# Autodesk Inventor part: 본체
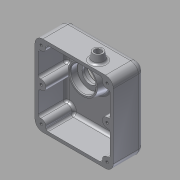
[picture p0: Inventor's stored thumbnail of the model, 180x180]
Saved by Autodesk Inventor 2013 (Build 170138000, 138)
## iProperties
Created: 2015-10
Part Number: 본체
Material: 알루미늄 6061
Document SubType Name: Modeling
Designer: mduedu
Density: 2.71 g/cm^3
Mass: 323.558 g
Surface Area: 515.791 cm^2
Volume: 119.394 cm^3
Author: mduedu
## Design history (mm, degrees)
sketch "스케치1"
  geometry: L1 (-50, -51.5)-(50, -51.5); L2 (50, -51.5)-(50, 51.5); L3 (50, 51.5)-(-50, 51.5); L4 (-50, 51.5)-(-50, -51.5); L5 (-50, -51.5)-(50, 51.5); L6 (50, -51.5)-(-50, 51.5); 1 further point
  constraints: 12 end point, 2 midpoint, 2 parallel, 1 horizontal, 1 perpendicular
  dimensions: "d0" = 100 distance of L3.end L2.end; "d1" = 103 distance of L2.end L1.end
extrude "돌출1" new body sketch "스케치1" distance "d2" = 40; taper "d3" = 0 deg
fillet "모깎기1" dims "d4" = 10
fillet "모깎기2" dims "d5" = 8
feature "쉘1" dims "d6" = 4
sketch "스케치2"
  geometry: L1 (-50, 41.5)-(-50, -41.5) reference; L2 (50, -41.5)-(50, 41.5) reference; L3 (-50, 0)-(50, 0); L4 (40, 51.5)-(-40, 51.5) reference; L5 (-40, -51.5)-(40, -51.5) reference; L6 (0, 51.5)-(0, -51.5); C1 r 6 at (-42, 43.5); C2 r 6 at (-42, 0); C3 r 6 at (-42, -43.5); C4 r 6 at (42, 43.5); C5 r 6 at (42, 0); C6 r 6 at (42, -43.5); 1 further point
  constraints: 6 centre point, 4 end point, 4 midpoint, 4 symmetric about line, 1 point on line, 1 vertical alignment, 4 other
  dimensions: "d7" = 12 diameter of C1; "d10" = 12 diameter of C2 (= d7); "d16" = 8 distance from line of C1.centre L1; "d17" = 8 distance from line of C1.centre L4
extrude "돌출2" join sketch "스케치2" stored distance "d11" = 0; taper "d12" = 0 deg
fillet "모깎기3" dims "d13" = 3
sketch "스케치3"
  geometry: A1 r 6 centre (-42, 43.5) between (-42.667, 37.537) and (-36.037, 44.167) reference; A2 r 6 centre (42, 43.5) between (36.037, 44.167) and (42.667, 37.537) reference; A3 r 6 centre (42, 0) between (42.667, 5.963) and (42.667, -5.963) reference; A4 r 6 centre (-42, 0) between (-42.667, -5.963) and (-42.667, 5.963) reference; A5 r 6 centre (-42, -43.5) between (-36.037, -44.167) and (-42.667, -37.537) reference; A6 r 6 centre (42, -43.5) between (42.667, -37.537) and (36.037, -44.167) reference; 7 further points
  constraints: 6 coincident
hole "구멍1" sketch "스케치3" at (-42, 43.5), (-42, 0), (-42, -43.5), (42, -43.5), (42, 0), (42, 43.5) diameter "d18" = 3.242; stored, may be unused: countersink angle "d22" = 90 deg, drill point angle "d24" = 118 deg; dims "d19" = 12, "d20" = 4, "d21" = 2, "d23" = 14
sketch "스케치4"
  geometry: L1 (90, 0)-(80, 0) reference; L2 (90, 0)-(90, 32) reference; C1 r 8 at (58.594, 12); 1 further point
  constraints: 1 centre point
  dimensions: "d25" = 16 diameter of C1; "d26" = 12 distance from line of L1 C1.centre; "d27" = 31.406 distance from line of C1.centre L2
extrude "돌출3" join sketch "스케치4" distance "d28" = 10; taper "d29" = -10 deg
sketch "스케치5"
  geometry: C1 r 8 at (0, 0) reference; C2 r 4 at (0, 0); 1 further point
  constraints: 1 centre point, 1 coincident
  dimensions: "d30" = 8 diameter of C2
extrude "돌출4" cut sketch "스케치5" stored distance "d31" = 0; taper "d32" = 0 deg
chamfer "모따기1" distance "d33" = 0.5; stored, may be unused: second distance "d34" = 2, angle "d35" = 45 deg
fillet "모깎기4" dims "d36" = 3
sketch "스케치6"
  geometry: L1 (73, 8)-(-7, 8) reference; L2 (-17, -2)-(-17, -85) reference; C1 r 21.5 at (23, -32); 1 further point
  constraints: 1 centre point
  dimensions: "d37" = 43 diameter of C1; "d38" = 40 distance from line of C1.centre L1; "d39" = 40 distance from line of C1.centre L2
extrude "돌출5" join sketch "스케치6" distance "d40" = 15; taper "d41" = -10 deg
hole "구멍2" diameter "d44" = 25; stored, may be unused: countersink angle "d48" = 90 deg, drill point angle "d50" = 0 deg; dims "d42" = 10, "d43" = 10, "d45" = 10, "d46" = 4, "d47" = 2, "d49" = 7
hole "구멍3" diameter "d53" = 20; stored, may be unused: countersink angle "d57" = 90 deg, drill point angle "d59" = 0 deg; dims "d51" = 10, "d52" = 10, "d54" = 10, "d55" = 32, "d56" = 9, "d58" = 7
chamfer "모따기2" distance "d60" = 1; stored, may be unused: second distance "d61" = 2, angle "d62" = 45 deg
sketch "스케치7"
  geometry: L1 (-50, 41.5)-(-50, -41.5) reference; L2 (-40, -51.5)-(40, -51.5) reference; 2 further points
  constraints: 1 other
  dimensions: "d63" = 50 distance from line of point (0, -21.5) L1; "d64" = 30 distance from line of point (0, -21.5) L2
feature "엠보싱1" sketch "스케치7" dims "d0" = 100, "d1" = 103, "d65" = 0.5, "d66" = 0
fillet "모깎기5" dims "d67" = 3
fillet "모깎기6" dims "d68" = 0.3
chamfer "모따기3" distance "d69" = 0.5; stored, may be unused: second distance "d70" = 2, angle "d71" = 45 deg
node "솔리드1"
